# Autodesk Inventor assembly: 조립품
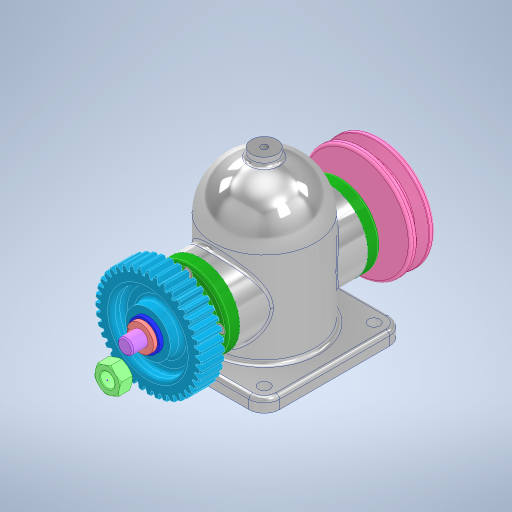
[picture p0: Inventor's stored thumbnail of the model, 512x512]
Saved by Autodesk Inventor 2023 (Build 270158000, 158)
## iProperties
Created: 2025-04
Part Number: 조립품
Document SubType Name: Assembly
Designer: User
Author: User
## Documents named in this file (14)
- C:\Users\User\Desktop\750406V1001\조립품.iam
- C:\Users\User\Desktop\750406V1001\본체.ipt
- C:\Users\User\Desktop\750406V1001\깊은 홈 볼 베어링 6203.ipt
- C:\Users\User\Desktop\750406V1001\축.ipt
- C:\Users\User\Desktop\750406V1001\커버.ipt
- C:\Users\User\Desktop\750406V1001\오일 실 26 38 8.ipt
- C:\Users\User\Desktop\750406V1001\6각 구멍붙이 볼트 M4x12.ipt
- C:\Users\User\Desktop\750406V1001\칼라.ipt
- C:\Users\User\Desktop\750406V1001\평행 키 5x5x12.ipt
- C:\Users\User\Desktop\750406V1001\스퍼기어.ipt
- C:\Users\User\Desktop\750406V1001\V 벨트 풀리.ipt
- C:\Users\User\Desktop\750406V1001\평와셔 M12.ipt
- C:\Users\User\Desktop\750406V1001\스프링 와셔 M12.ipt
- C:\Users\User\Desktop\750406V1001\6각 너트 M12x1.ipt
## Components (11 placed, 3 different names)
1. 6각 구멍붙이 볼트 M4x12:1
2. 6각 구멍붙이 볼트 M4x12:2
3. 6각 구멍붙이 볼트 M4x12:3
4. 6각 구멍붙이 볼트 M4x12:4
5. 6각 구멍붙이 볼트 M4x12:5
6. 6각 구멍붙이 볼트 M4x12:6
7. 6각 구멍붙이 볼트 M4x12:7
8. 6각 구멍붙이 볼트 M4x12:8
9. V 벨트 풀리:1
10. 6각 너트 M12x1:1
11. 6각 너트 M12x1:2
